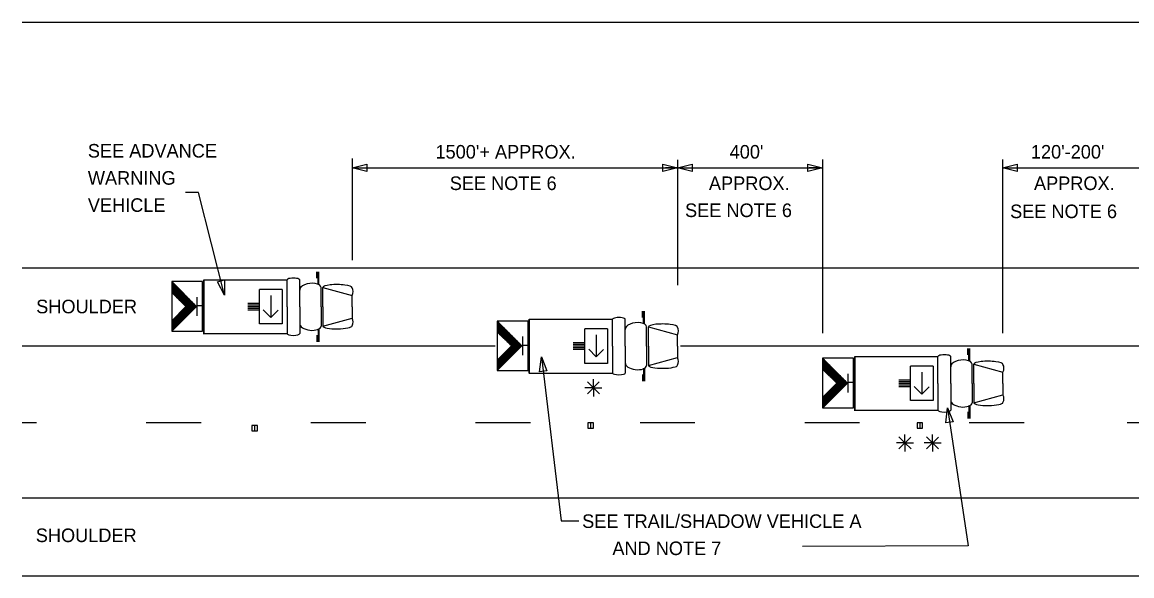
# Model space of a CAD drawing. Extents: x 1373848 to 1374003, y 380642 to 381248.
# Drawn here: x 1373848.14 to 1373897.19, y 381021.44 to 381045.91 of the extents above; entities that cross this region are included whole.
import ezdxf

# ---------------------------------------------------------------- set-up
doc = ezdxf.new("R2010")
doc.units = 0
doc.layers.add('Level 1', color=7, linetype='Continuous')
doc.layers.add('Working Level 1', color=7, linetype='Continuous')

msp = doc.modelspace()

# ---------------------------------------------------------------- linework, layer by layer
at = {"layer": 'Level 1'}
msp.add_lwpolyline([(1373889.04, 381028.863), (1373889.96, 381022.759), (1373882.632, 381022.731)], dxfattribs=at)
at = {"layer": 'Working Level 1'}
for p, q in [((1373848.144, 381045.913), (1373928.15, 381045.913)), ((1373862.725, 381039.886), (1373862.725, 381035.388)), ((1373877.111, 381039.827), (1373877.111, 381034.282)), ((1373883.525, 381039.85), (1373883.525, 381032.162)), ((1373891.479, 381039.85), (1373891.479, 381032.162)), ((1373862.725, 381039.48), (1373863.281, 381039.48)), ((1373862.725, 381039.48), (1373877.111, 381039.48)), ((1373877.111, 381039.48), (1373876.583, 381039.48)), ((1373877.111, 381039.48), (1373877.729, 381039.48)), ((1373877.111, 381039.48), (1373883.525, 381039.48)), ((1373883.452, 381039.48), (1373882.924, 381039.48)), ((1373891.479, 381039.48), (1373892.097, 381039.48)), ((1373891.479, 381039.48), (1373897.894, 381039.48)), ((1373848.144, 381035.059), (1373928.15, 381035.059)), ((1373861.175, 381034.593), (1373861.175, 381034.884)), ((1373861.221, 381034.313), (1373861.221, 381034.884)), ((1373861.26, 381034.313), (1373861.26, 381034.884)), ((1373854.752, 381034.445), (1373855.848, 381033.35)), ((1373856.163, 381034.495), (1373856.163, 381032.118)), ((1373856.172, 381034.523), (1373856.172, 381032.146)), ((1373856.172, 381032.145), (1373856.172, 381034.522)), ((1373856.172, 381034.522), (1373859.852, 381034.522)), ((1373859.852, 381033.334), (1373859.852, 381034.522)), ((1373860.415, 381033.334), (1373860.415, 381034.522)), ((1373861.36, 381033.334), (1373861.36, 381034.19)), ((1373861.438, 381034.19), (1373862.725, 381033.838)), ((1373861.438, 381033.334), (1373861.438, 381034.19)), ((1373854.752, 381033.969), (1373855.38, 381033.343)), ((1373855.885, 381032.938), (1373855.885, 381033.762)), ((1373859.636, 381034.094), (1373858.63, 381034.094)), ((1373858.63, 381032.573), (1373858.63, 381034.094)), ((1373859.133, 381033.836), (1373859.133, 381032.863)), ((1373859.636, 381034.094), (1373859.636, 381032.573)), ((1373862.725, 381033.334), (1373862.725, 381033.838)), ((1373854.752, 381032.717), (1373855.38, 381033.343)), ((1373854.758, 381032.26), (1373855.848, 381033.35)), ((1373856.114, 381033.37), (1373855.878, 381033.37)), ((1373858.63, 381033.485), (1373858.118, 381033.485)), ((1373858.63, 381033.409), (1373858.118, 381033.409)), ((1373858.63, 381033.333), (1373858.118, 381033.333)), ((1373858.63, 381033.257), (1373858.118, 381033.257)), ((1373858.63, 381033.182), (1373858.118, 381033.182)), ((1373859.133, 381032.863), (1373858.802, 381033.194)), ((1373859.133, 381032.863), (1373859.456, 381033.186)), ((1373859.852, 381033.334), (1373859.852, 381032.146)), ((1373860.415, 381033.334), (1373860.415, 381032.146)), ((1373861.36, 381033.334), (1373861.36, 381032.478)), ((1373861.438, 381033.334), (1373861.438, 381032.478)), ((1373862.725, 381033.334), (1373862.725, 381032.83)), ((1373875.562, 381032.852), (1373875.562, 381033.143)), ((1373875.608, 381032.572), (1373875.608, 381033.143)), ((1373875.647, 381032.572), (1373875.647, 381033.143)), ((1373861.438, 381032.478), (1373862.725, 381032.83)), ((1373869.139, 381032.704), (1373870.234, 381031.609)), ((1373870.55, 381032.754), (1373870.55, 381030.377)), ((1373870.559, 381030.404), (1373870.559, 381032.781)), ((1373870.559, 381032.781), (1373870.559, 381030.404)), ((1373870.559, 381032.781), (1373874.238, 381032.781)), ((1373874.238, 381031.593), (1373874.238, 381032.781)), ((1373874.802, 381031.593), (1373874.802, 381032.781)), ((1373856.172, 381032.146), (1373859.852, 381032.146)), ((1373859.636, 381032.573), (1373858.63, 381032.573)), ((1373861.221, 381032.354), (1373861.221, 381031.784)), ((1373861.26, 381032.354), (1373861.26, 381031.784)), ((1373869.139, 381032.228), (1373869.767, 381031.602)), ((1373874.022, 381032.353), (1373873.017, 381032.353)), ((1373873.017, 381030.832), (1373873.017, 381032.353)), ((1373874.022, 381032.353), (1373874.022, 381030.832)), ((1373875.746, 381031.593), (1373875.746, 381032.449)), ((1373875.825, 381032.449), (1373877.111, 381032.097)), ((1373875.825, 381031.593), (1373875.825, 381032.449)), ((1373861.175, 381032.074), (1373861.175, 381031.784)), ((1373870.271, 381031.197), (1373870.271, 381032.021)), ((1373873.017, 381031.744), (1373872.504, 381031.744)), ((1373873.017, 381031.668), (1373872.504, 381031.668)), ((1373873.519, 381032.095), (1373873.519, 381031.122)), ((1373877.111, 381031.593), (1373877.111, 381032.097)), ((1373848.144, 381031.611), (1373862.771, 381031.611)), ((1373862.748, 381031.611), (1373869.044, 381031.611)), ((1373869.139, 381030.976), (1373869.767, 381031.602)), ((1373869.145, 381030.519), (1373870.234, 381031.609)), ((1373870.501, 381031.628), (1373870.265, 381031.628)), ((1373873.017, 381031.592), (1373872.504, 381031.592)), ((1373873.017, 381031.516), (1373872.504, 381031.516)), ((1373873.017, 381031.44), (1373872.504, 381031.44)), ((1373873.519, 381031.122), (1373873.189, 381031.453)), ((1373873.519, 381031.122), (1373873.842, 381031.445)), ((1373874.238, 381031.593), (1373874.238, 381030.404)), ((1373874.802, 381031.593), (1373874.802, 381030.404)), ((1373875.746, 381031.593), (1373875.746, 381030.737)), ((1373875.825, 381031.593), (1373875.825, 381030.737)), ((1373877.111, 381031.593), (1373877.111, 381031.089)), ((1373877.242, 381031.611), (1373928.15, 381031.611)), ((1373889.948, 381031.204), (1373889.948, 381031.495)), ((1373889.994, 381030.924), (1373889.994, 381031.495)), ((1373890.034, 381030.924), (1373890.034, 381031.495)), ((1373874.022, 381030.832), (1373873.017, 381030.832)), ((1373875.825, 381030.737), (1373877.111, 381031.089)), ((1373883.525, 381031.056), (1373884.621, 381029.961)), ((1373884.936, 381031.106), (1373884.936, 381028.729)), ((1373884.945, 381031.134), (1373884.945, 381028.757)), ((1373884.945, 381028.756), (1373884.945, 381031.133)), ((1373884.945, 381031.133), (1373888.625, 381031.133)), ((1373888.409, 381030.705), (1373887.403, 381030.705)), ((1373887.403, 381029.184), (1373887.403, 381030.705)), ((1373888.409, 381030.705), (1373888.409, 381029.184)), ((1373888.625, 381029.945), (1373888.625, 381031.133)), ((1373889.188, 381029.945), (1373889.188, 381031.133)), ((1373890.133, 381029.945), (1373890.133, 381030.801)), ((1373890.211, 381030.801), (1373891.498, 381030.449)), ((1373890.211, 381029.945), (1373890.211, 381030.801)), ((1373870.559, 381030.404), (1373874.238, 381030.404)), ((1373875.562, 381030.333), (1373875.562, 381030.042)), ((1373875.608, 381030.613), (1373875.608, 381030.042)), ((1373875.647, 381030.613), (1373875.647, 381030.042)), ((1373883.525, 381030.58), (1373884.154, 381029.954)), ((1373884.658, 381029.549), (1373884.658, 381030.373)), ((1373887.906, 381030.447), (1373887.906, 381029.474)), ((1373891.498, 381029.945), (1373891.498, 381030.449)), ((1373873.395, 381029.749), (1373873.018, 381029.749)), ((1373873.395, 381029.749), (1373873.129, 381030.015)), ((1373873.395, 381029.749), (1373873.129, 381029.483)), ((1373873.388, 381029.744), (1373873.655, 381030.01)), ((1373873.395, 381029.749), (1373873.395, 381030.126)), ((1373873.395, 381029.749), (1373873.661, 381029.483)), ((1373873.395, 381029.749), (1373873.395, 381029.373)), ((1373873.395, 381029.749), (1373873.771, 381029.749)), ((1373883.525, 381029.328), (1373884.154, 381029.954)), ((1373883.531, 381028.871), (1373884.621, 381029.961)), ((1373884.887, 381029.981), (1373884.651, 381029.981)), ((1373887.403, 381030.096), (1373886.891, 381030.096)), ((1373887.403, 381030.02), (1373886.891, 381030.02)), ((1373887.403, 381029.944), (1373886.891, 381029.944)), ((1373887.403, 381029.868), (1373886.891, 381029.868)), ((1373887.403, 381029.793), (1373886.891, 381029.793)), ((1373887.906, 381029.474), (1373887.575, 381029.805)), ((1373887.906, 381029.474), (1373888.229, 381029.797)), ((1373888.625, 381029.945), (1373888.625, 381028.757)), ((1373889.188, 381029.945), (1373889.188, 381028.757)), ((1373890.133, 381029.945), (1373890.133, 381029.089)), ((1373890.211, 381029.945), (1373890.211, 381029.089)), ((1373891.498, 381029.945), (1373891.498, 381029.441)), ((1373890.211, 381029.089), (1373891.498, 381029.441)), ((1373884.945, 381028.757), (1373888.625, 381028.757)), ((1373888.409, 381029.184), (1373887.403, 381029.184)), ((1373889.994, 381028.965), (1373889.994, 381028.395)), ((1373890.034, 381028.965), (1373890.034, 381028.395)), ((1373889.948, 381028.685), (1373889.948, 381028.395)), ((1373858.296, 381028.088), (1373858.295, 381027.845)), ((1373858.295, 381027.845), (1373858.538, 381027.845)), ((1373858.538, 381028.088), (1373858.296, 381028.088)), ((1373858.417, 381028.088), (1373858.417, 381027.845)), ((1373858.538, 381027.845), (1373858.538, 381028.088)), ((1373873.15, 381028.209), (1373873.149, 381027.966)), ((1373873.149, 381027.966), (1373873.392, 381027.966)), ((1373873.392, 381028.209), (1373873.15, 381028.209)), ((1373873.272, 381028.209), (1373873.271, 381027.966)), ((1373873.392, 381027.966), (1373873.392, 381028.209)), ((1373887.94, 381028.209), (1373887.697, 381028.209)), ((1373887.697, 381028.209), (1373887.697, 381027.966)), ((1373887.697, 381027.966), (1373887.94, 381027.966)), ((1373887.819, 381028.209), (1373887.819, 381027.966)), ((1373887.94, 381027.966), (1373887.94, 381028.209)), ((1373887.166, 381027.314), (1373886.79, 381027.314)), ((1373887.166, 381027.314), (1373886.9, 381027.58)), ((1373887.166, 381027.314), (1373886.9, 381027.048)), ((1373887.16, 381027.309), (1373887.426, 381027.575)), ((1373887.166, 381027.314), (1373887.166, 381027.69)), ((1373887.166, 381027.314), (1373887.432, 381027.048)), ((1373887.166, 381027.314), (1373887.166, 381026.938)), ((1373887.166, 381027.314), (1373887.542, 381027.314)), ((1373888.383, 381027.314), (1373888.007, 381027.314)), ((1373888.383, 381027.314), (1373888.117, 381027.58)), ((1373888.383, 381027.314), (1373888.117, 381027.048)), ((1373888.377, 381027.309), (1373888.643, 381027.575)), ((1373888.383, 381027.314), (1373888.383, 381027.69)), ((1373888.383, 381027.314), (1373888.649, 381027.048)), ((1373888.383, 381027.314), (1373888.383, 381026.938)), ((1373888.383, 381027.314), (1373888.759, 381027.314)), ((1373848.144, 381024.889), (1373912.979, 381024.889)), ((1373848.144, 381021.441), (1373909.291, 381021.441))]:
    msp.add_line(p, q, dxfattribs=at)
for points in [[(1373863.373, 381039.318), (1373862.723, 381039.48), (1373863.373, 381039.643)], [(1373876.461, 381039.643), (1373877.111, 381039.48), (1373876.461, 381039.318)], [(1373877.761, 381039.318), (1373877.111, 381039.48), (1373877.761, 381039.643)], [(1373882.875, 381039.643), (1373883.525, 381039.48), (1373882.875, 381039.318)], [(1373892.129, 381039.318), (1373891.479, 381039.48), (1373892.129, 381039.643)], [(1373854.752, 381034.445), (1373854.752, 381032.259), (1373856.118, 381032.259), (1373856.118, 381034.445)], [(1373857.092, 381034.517), (1373857.094, 381033.847), (1373856.777, 381034.437)], [(1373869.139, 381032.704), (1373869.139, 381030.518), (1373870.504, 381030.518), (1373870.504, 381032.704)], [(1373871.014, 381030.462), (1373871.099, 381031.127), (1373871.337, 381030.501)], [(1373883.525, 381031.056), (1373883.525, 381028.87), (1373884.891, 381028.87), (1373884.891, 381031.056)], [(1373888.976, 381028.196), (1373889.04, 381028.863), (1373889.298, 381028.245)]]:
    msp.add_lwpolyline(points, close=True, dxfattribs=at)
for points in [[(1373857.094, 381033.847), (1373855.941, 381038.391), (1373855.365, 381038.391)], [(1373854.752, 381034.393), (1373855.33, 381033.392)], [(1373854.752, 381034.308), (1373855.216, 381033.504)], [(1373854.752, 381034.221), (1373855.102, 381033.616)], [(1373854.752, 381034.135), (1373854.987, 381033.729)], [(1373854.801, 381034.397), (1373855.566, 381033.07)], [(1373854.918, 381034.279), (1373855.598, 381033.101)], [(1373855.035, 381034.162), (1373855.63, 381033.133)], [(1373854.752, 381034.049), (1373854.873, 381033.841)], [(1373854.752, 381033.963), (1373854.758, 381033.953)], [(1373855.153, 381034.044), (1373855.661, 381033.164)], [(1373855.27, 381033.927), (1373855.693, 381033.196)], [(1373855.388, 381033.809), (1373855.725, 381033.225)], [(1373855.505, 381033.692), (1373855.758, 381033.255)], [(1373855.177, 381033.141), (1373855.345, 381032.85)], [(1373855.208, 381033.172), (1373855.377, 381032.881)], [(1373855.24, 381033.205), (1373855.409, 381032.913)], [(1373855.272, 381033.236), (1373855.44, 381032.944)], [(1373855.303, 381033.267), (1373855.472, 381032.975)], [(1373855.334, 381033.299), (1373855.504, 381033.007)], [(1373855.367, 381033.331), (1373855.535, 381033.038)], [(1373855.623, 381033.576), (1373855.787, 381033.291)], [(1373855.732, 381033.468), (1373855.816, 381033.322)], [(1373854.752, 381032.671), (1373854.903, 381032.409)], [(1373854.767, 381032.732), (1373854.935, 381032.442)], [(1373854.799, 381032.764), (1373854.966, 381032.472)], [(1373854.83, 381032.794), (1373854.997, 381032.504)], [(1373854.862, 381032.827), (1373855.03, 381032.535)], [(1373854.893, 381032.858), (1373855.061, 381032.567)], [(1373854.925, 381032.889), (1373855.092, 381032.598)], [(1373854.956, 381032.92), (1373855.124, 381032.629)], [(1373854.988, 381032.952), (1373855.156, 381032.661)], [(1373855.02, 381032.984), (1373855.187, 381032.692)], [(1373855.051, 381033.015), (1373855.219, 381032.724)], [(1373855.083, 381033.047), (1373855.251, 381032.755)], [(1373855.113, 381033.078), (1373855.282, 381032.787)], [(1373855.146, 381033.11), (1373855.314, 381032.817)], [(1373869.139, 381032.652), (1373869.717, 381031.651)], [(1373869.188, 381032.656), (1373869.953, 381031.329)], [(1373854.752, 381032.584), (1373854.871, 381032.378)], [(1373854.752, 381032.498), (1373854.84, 381032.347)], [(1373854.752, 381032.412), (1373854.809, 381032.315)], [(1373854.752, 381032.326), (1373854.776, 381032.284)], [(1373869.139, 381032.566), (1373869.602, 381031.763)], [(1373869.139, 381032.48), (1373869.488, 381031.875)], [(1373869.139, 381032.394), (1373869.374, 381031.988)], [(1373869.139, 381032.308), (1373869.259, 381032.1)], [(1373869.139, 381032.221), (1373869.145, 381032.212)], [(1373869.304, 381032.537), (1373869.985, 381031.36)], [(1373869.422, 381032.421), (1373870.016, 381031.392)], [(1373869.54, 381032.303), (1373870.048, 381031.423)], [(1373869.657, 381032.186), (1373870.079, 381031.455)], [(1373869.774, 381032.068), (1373870.112, 381031.484)], [(1373869.892, 381031.95), (1373870.144, 381031.514)], [(1373870.01, 381031.834), (1373870.173, 381031.55)], [(1373870.118, 381031.727), (1373870.203, 381031.58)], [(1373869.343, 381031.179), (1373869.511, 381030.888)], [(1373869.375, 381031.211), (1373869.543, 381030.919)], [(1373869.406, 381031.242), (1373869.574, 381030.951)], [(1373869.438, 381031.274), (1373869.606, 381030.983)], [(1373869.469, 381031.306), (1373869.637, 381031.014)], [(1373869.5, 381031.337), (1373869.669, 381031.045)], [(1373869.532, 381031.369), (1373869.701, 381031.076)], [(1373869.564, 381031.4), (1373869.732, 381031.109)], [(1373869.595, 381031.431), (1373869.764, 381031.14)], [(1373869.627, 381031.463), (1373869.795, 381031.171)], [(1373869.658, 381031.495), (1373869.827, 381031.203)], [(1373869.69, 381031.526), (1373869.858, 381031.234)], [(1373869.721, 381031.558), (1373869.89, 381031.266)], [(1373869.753, 381031.589), (1373869.922, 381031.297)], [(1373869.139, 381030.93), (1373869.29, 381030.668)], [(1373869.139, 381030.843), (1373869.258, 381030.637)], [(1373869.139, 381030.757), (1373869.227, 381030.605)], [(1373869.139, 381030.671), (1373869.195, 381030.574)], [(1373869.154, 381030.991), (1373869.321, 381030.7)], [(1373869.185, 381031.022), (1373869.353, 381030.731)], [(1373869.217, 381031.053), (1373869.384, 381030.763)], [(1373869.249, 381031.086), (1373869.416, 381030.794)], [(1373869.279, 381031.116), (1373869.448, 381030.826)], [(1373869.311, 381031.148), (1373869.479, 381030.857)], [(1373871.099, 381031.127), (1373871.961, 381023.868), (1373872.752, 381023.868)], [(1373883.525, 381031.004), (1373884.104, 381030.003)], [(1373883.525, 381030.919), (1373883.989, 381030.115)], [(1373883.525, 381030.832), (1373883.875, 381030.227)], [(1373883.525, 381030.746), (1373883.76, 381030.34)], [(1373883.574, 381031.008), (1373884.339, 381029.681)], [(1373883.691, 381030.89), (1373884.371, 381029.712)], [(1373883.809, 381030.773), (1373884.403, 381029.744)], [(1373869.139, 381030.585), (1373869.163, 381030.543)], [(1373883.525, 381030.66), (1373883.646, 381030.452)], [(1373883.525, 381030.574), (1373883.531, 381030.564)], [(1373883.926, 381030.655), (1373884.434, 381029.775)], [(1373884.043, 381030.538), (1373884.466, 381029.807)], [(1373884.161, 381030.42), (1373884.499, 381029.836)], [(1373884.279, 381030.303), (1373884.531, 381029.866)], [(1373884.397, 381030.186), (1373884.56, 381029.902)], [(1373883.887, 381029.689), (1373884.055, 381029.398)], [(1373883.919, 381029.721), (1373884.087, 381029.428)], [(1373883.95, 381029.752), (1373884.118, 381029.461)], [(1373883.982, 381029.783), (1373884.15, 381029.492)], [(1373884.013, 381029.816), (1373884.182, 381029.524)], [(1373884.045, 381029.847), (1373884.213, 381029.555)], [(1373884.077, 381029.878), (1373884.245, 381029.586)], [(1373884.108, 381029.91), (1373884.277, 381029.618)], [(1373884.14, 381029.941), (1373884.308, 381029.649)], [(1373884.505, 381030.079), (1373884.589, 381029.933)], [(1373883.525, 381029.282), (1373883.676, 381029.02)], [(1373883.525, 381029.195), (1373883.644, 381028.989)], [(1373883.54, 381029.343), (1373883.708, 381029.053)], [(1373883.572, 381029.375), (1373883.74, 381029.083)], [(1373883.603, 381029.405), (1373883.77, 381029.115)], [(1373883.635, 381029.438), (1373883.803, 381029.146)], [(1373883.666, 381029.469), (1373883.834, 381029.178)], [(1373883.698, 381029.5), (1373883.865, 381029.209)], [(1373883.729, 381029.531), (1373883.897, 381029.24)], [(1373883.761, 381029.563), (1373883.929, 381029.272)], [(1373883.793, 381029.595), (1373883.961, 381029.303)], [(1373883.824, 381029.626), (1373883.992, 381029.335)], [(1373883.856, 381029.658), (1373884.024, 381029.366)], [(1373883.525, 381029.109), (1373883.613, 381028.958)], [(1373883.525, 381029.023), (1373883.582, 381028.926)], [(1373883.525, 381028.937), (1373883.549, 381028.895)], [(1373848.144, 381028.212), (1373848.781, 381028.212)], [(1373853.631, 381028.212), (1373856.056, 381028.212)], [(1373860.906, 381028.212), (1373863.331, 381028.212)], [(1373868.181, 381028.212), (1373870.607, 381028.212)], [(1373875.457, 381028.212), (1373877.882, 381028.212)], [(1373882.732, 381028.212), (1373885.158, 381028.212)], [(1373890.008, 381028.212), (1373892.433, 381028.212)], [(1373896.983, 381028.212), (1373899.408, 381028.212)]]:
    msp.add_lwpolyline(points, dxfattribs=at)
for centre in [(1373862.41, 381034.006), (1373862.41, 381032.661), (1373876.796, 381032.265), (1373876.796, 381030.92), (1373891.183, 381030.617), (1373891.183, 381029.272)]:
    msp.add_arc(centre, 0.357, 331.8801, 28.1199, dxfattribs=at)
for centre, major_axis, ratio, start_param, end_param in [((1373860.133, 381034.522), (0.282, 0), 0.269913, 0, 3.141593), ((1373860.887, 381034.131), (0.472, 0.058), 0.503092, 0, 3.141593), ((1373862.081, 381034.183), (0.643, -0.007), 0.2034, 0, 3.141593), ((1373874.52, 381032.781), (0.282, 0), 0.269913, 0, 3.141593), ((1373875.274, 381032.39), (0.472, 0.058), 0.503092, 0, 3.141593), ((1373860.133, 381032.146), (0.282, 0), 0.269913, 3.141593, 6.283185), ((1373860.887, 381032.536), (0.472, -0.058), 0.503092, 3.141593, 6.283185), ((1373862.081, 381032.485), (0.643, 0.007), 0.2034, 3.141593, 6.283185), ((1373876.468, 381032.441), (0.643, -0.007), 0.2034, 0, 3.141593), ((1373888.907, 381031.133), (0.282, 0), 0.269913, 0, 3.141593), ((1373875.274, 381030.795), (0.472, -0.058), 0.503092, 3.141593, 6.283185), ((1373876.468, 381030.744), (0.643, 0.007), 0.2034, 3.141593, 6.283185), ((1373889.661, 381030.742), (0.472, 0.058), 0.503092, 0, 3.141593), ((1373890.855, 381030.794), (0.643, -0.007), 0.2034, 0, 3.141593), ((1373874.52, 381030.404), (0.282, 0), 0.269913, 3.141593, 6.283185), ((1373889.661, 381029.147), (0.472, -0.058), 0.503092, 3.141593, 6.283185), ((1373888.907, 381028.757), (0.282, 0), 0.269913, 3.141593, 6.283185), ((1373890.855, 381029.096), (0.643, 0.007), 0.2034, 3.141593, 6.283185)]:
    msp.add_ellipse(centre, major_axis=major_axis, ratio=ratio, start_param=start_param, end_param=end_param, dxfattribs=at)

# ---------------------------------------------------------------- texts
for s, p in [('SEE ADVANCE ', (1373851.047, 381039.929)), ("1500'+ APPROX.", (1373866.412, 381039.884)), ("400'", (1373879.416, 381039.884)), ("120'-200'", (1373892.731, 381039.884)), ('WARNING ', (1373851.047, 381038.729)), ('SEE NOTE 6', (1373867.043, 381038.493)), ('APPROX.', (1373878.499, 381038.493)), ('APPROX.', (1373892.868, 381038.493)), ('VEHICLE', (1373851.047, 381037.529)), ('SEE NOTE 6', (1373877.444, 381037.299)), ('SEE NOTE 6', (1373891.812, 381037.251)), ('SEE TRAIL/SHADOW VEHICLE A ', (1373872.895, 381023.557)), ('      AND NOTE 7', (1373872.895, 381022.357))]:
    msp.add_text(s, height=0.6, dxfattribs=at).set_placement(p)
for p in [(1373848.762, 381033.044), (1373848.745, 381022.931)]:
    msp.add_text('SHOULDER', height=0.6, rotation=0, dxfattribs=at).set_placement(p)

doc.saveas('drawing.dxf')
